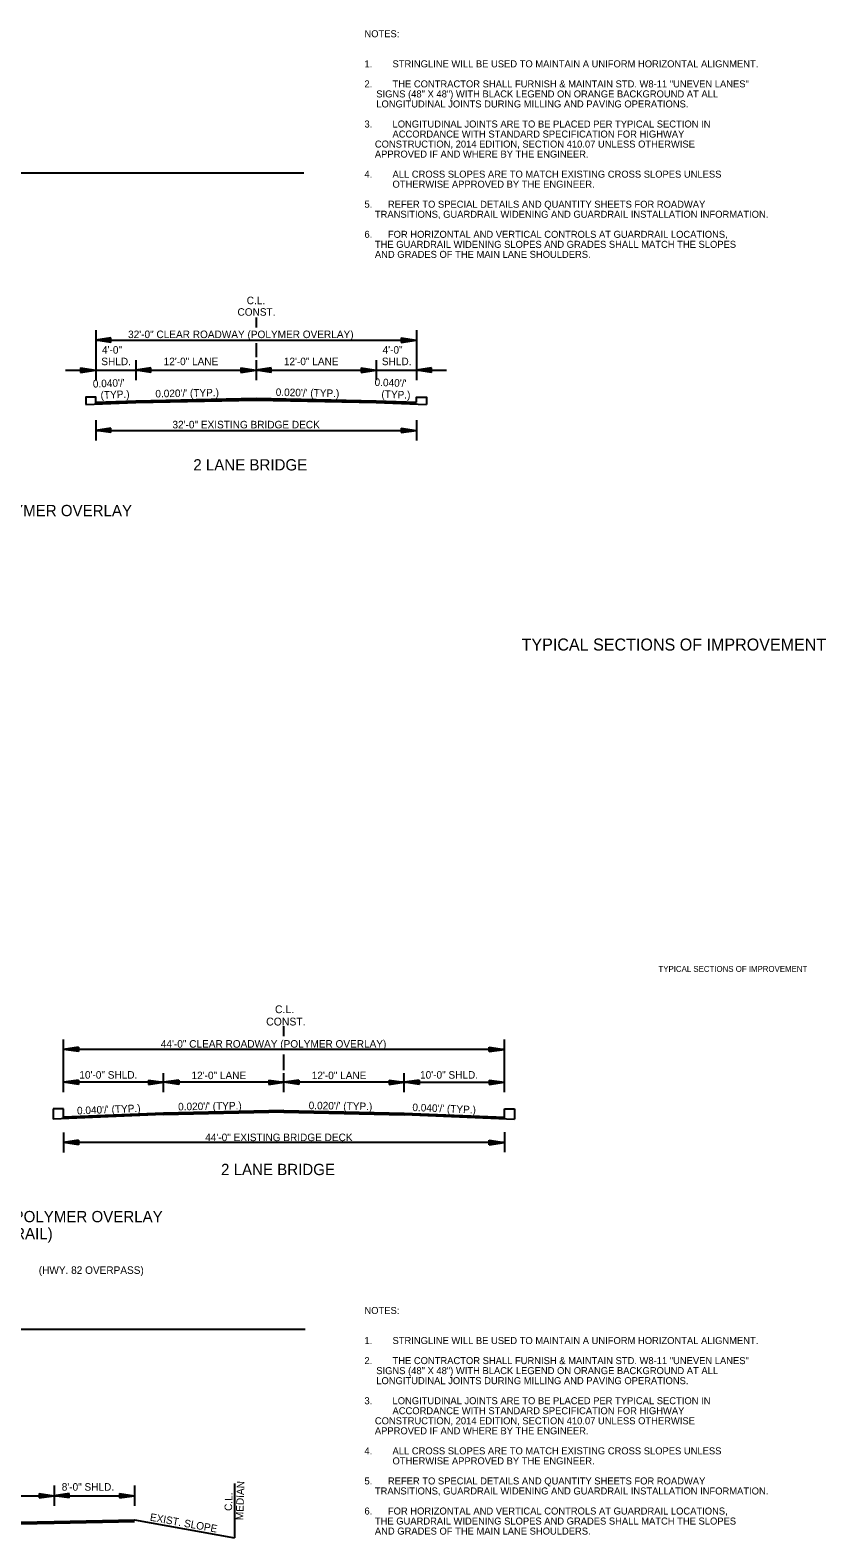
# Model space of a CAD drawing. Extents: x 545241 to 1930787, y -1971772 to 596640.
# Drawn here: x 547474 to 548268, y -1968756 to -1967253 of the extents above; entities that cross this region are included whole.
import ezdxf

# ---------------------------------------------------------------- set-up
doc = ezdxf.new("R2010")
doc.units = 0
for name, color, linetype in [('R_Border', 7, 'Continuous'), ('R_Border Notes', 7, 'Continuous'), ('R_Border Prem', 7, 'Continuous'), ('R_Draft', 7, 'Continuous')]:
    doc.layers.add(name, color=color, linetype=linetype)

# ---------------------------------------------------------------- blocks, each defined once
blk = doc.blocks.new('ARROW')
at = {"layer": 'R_Draft'}
for p, q in [((-2, 0.3), (0, 0)), ((-2, 0.3), (-2, -0.3)), ((-2, 0.25), (-0.334, 0)), ((-2, 0.199), (-0.678, 0)), ((-2, 0.149), (-1.011, 0)), ((-2, 0.097), (-1.35, 0)), ((-2, 0.047), (-1.684, 0)), ((-2, -0.3), (0, 0)), ((-2, -0.098), (-1.35, 0)), ((-2, -0.199), (-0.678, 0)), ((-2, -0.25), (-0.334, 0)), ((-2, -0.149), (-1.011, 0)), ((-2, -0.047), (-1.684, 0))]:
    blk.add_line(p, q, dxfattribs=at)

msp = doc.modelspace()

# ---------------------------------------------------------------- linework, layer by layer
at = {"layer": 'R_Border'}
for p, q in [((546718.9, -1967395.3), (547746.9, -1967395.3)), ((547699.2, -1967539.5), (547699.2, -1967549.5)), ((547539.2, -1967552), (547539.2, -1967602)), ((547859.2, -1967552), (547859.2, -1967602)), ((547539.2, -1967562), (547859.2, -1967562)), ((547699.2, -1967565), (547699.2, -1967579)), ((547579.2, -1967582), (547579.2, -1967602)), ((547699.2, -1967582), (547699.2, -1967602)), ((547819.2, -1967582), (547819.2, -1967602)), ((547509.2, -1967592), (547889.2, -1967592)), ((547539.2, -1967642), (547539.2, -1967662)), ((547859.2, -1967642), (547859.2, -1967662)), ((547539.2, -1967652), (547859.2, -1967652)), ((547507, -1968328.6), (547496.8, -1968328.6)), ((547496.8, -1968328.6), (547496.8, -1968338.8)), ((547507, -1968338), (547507, -1968328.6)), ((547947, -1968338), (547947, -1968328.6)), ((547947, -1968328.6), (547957.1, -1968328.6)), ((547957.1, -1968328.6), (547957.1, -1968338.8)), ((546720.3, -1968548.2), (547748.2, -1968548.2)), ((547497.8, -1968704.4), (547497.8, -1968724.4)), ((547577.8, -1968704.4), (547577.8, -1968724.4)), ((547677.8, -1968702.2), (547677.8, -1968756.4)), ((547177.8, -1968714.4), (547577.8, -1968714.4)), ((547577.8, -1968738.4), (547677.8, -1968756.4))]:
    msp.add_line(p, q, dxfattribs=at)
for points in [[(547539.2, -1967625.5), (547539.2, -1967619), (547529.2, -1967619), (547529.2, -1967626.2)], [(547529.2, -1967626.2), (547579.2, -1967624.2), (547699.2, -1967621.8), (547819.2, -1967624.2), (547869.2, -1967626.2)], [(547539.2, -1967624), (547579.2, -1967622.4), (547699.2, -1967620), (547819.2, -1967622.4), (547859.2, -1967624)], [(547539.2, -1967624.3), (547579.2, -1967622.7), (547699.2, -1967620.3), (547819.2, -1967622.7), (547859.2, -1967624.3)], [(547539.2, -1967624.6), (547579.2, -1967623), (547699.2, -1967620.6), (547819.2, -1967623), (547859.2, -1967624.6)], [(547539.2, -1967624.9), (547579.2, -1967623.3), (547699.2, -1967620.9), (547819.2, -1967623.3), (547859.2, -1967624.9)], [(547539.2, -1967625.2), (547579.2, -1967623.6), (547699.2, -1967621.2), (547819.2, -1967623.6), (547859.2, -1967625.2)], [(547539.2, -1967625.5), (547579.2, -1967623.9), (547699.2, -1967621.5), (547819.2, -1967623.9), (547859.2, -1967625.5)], [(547859.2, -1967624), (547859.2, -1967619), (547869.2, -1967619), (547869.2, -1967626.2)], [(547177.8, -1968748), (547257.8, -1968744.8), (547377.8, -1968742.4), (547497.8, -1968740), (547577.8, -1968738.4)], [(547177.8, -1968748.3), (547257.8, -1968745.1), (547377.8, -1968742.7), (547497.8, -1968740.3), (547577.8, -1968738.7)], [(547177.8, -1968748.6), (547257.8, -1968745.4), (547377.8, -1968743), (547497.8, -1968740.6), (547577.8, -1968739)], [(547177.8, -1968748.9), (547257.8, -1968745.7), (547377.8, -1968743.3), (547497.8, -1968740.9), (547577.8, -1968739.3)], [(547177.8, -1968749.2), (547257.8, -1968746), (547377.8, -1968743.6), (547497.8, -1968741.2), (547577.8, -1968739.6)], [(547177.8, -1968749.5), (547257.8, -1968746.3), (547377.8, -1968743.9), (547497.8, -1968741.5), (547577.8, -1968739.9)], [(547177.8, -1968749.8), (547257.8, -1968746.6), (547377.8, -1968744.2), (547497.8, -1968741.8), (547577.8, -1968740.2)]]:
    msp.add_lwpolyline(points, dxfattribs=at)
at = {"layer": 'R_Draft'}
for p, q in [((547727, -1968256.3), (547727, -1968246.3)), ((547507, -1968312.1), (547507, -1968259.4)), ((547947, -1968312.1), (547947, -1968259.4)), ((547522, -1968267.1), (547507, -1968269.3)), ((547947, -1968269.3), (547507, -1968269.3)), ((547522, -1968271.6), (547507, -1968269.3)), ((547522, -1968267.4), (547509.5, -1968269.3)), ((547522, -1968271.2), (547509.5, -1968269.3)), ((547522, -1968267.8), (547512, -1968269.3)), ((547522, -1968270.8), (547512, -1968269.3)), ((547522, -1968268.2), (547514.5, -1968269.3)), ((547522, -1968270.4), (547514.5, -1968269.3)), ((547522, -1968268.6), (547517.1, -1968269.3)), ((547522, -1968270), (547517.1, -1968269.3)), ((547522, -1968268.9), (547519.6, -1968269.3)), ((547522, -1968269.7), (547519.6, -1968269.3)), ((547522, -1968267.1), (547522, -1968271.6)), ((547897, -1968269.3), (547617, -1968269.3)), ((547727, -1968290.1), (547727, -1968274.4)), ((547932, -1968267.1), (547947, -1968269.3)), ((547932, -1968271.6), (547932, -1968267.1)), ((547932, -1968267.4), (547944.5, -1968269.3)), ((547932, -1968267.8), (547941.9, -1968269.3)), ((547932, -1968268.2), (547939.4, -1968269.3)), ((547932, -1968268.6), (547936.8, -1968269.3)), ((547932, -1968268.9), (547934.3, -1968269.3)), ((547932, -1968271.6), (547947, -1968269.3)), ((547932, -1968270), (547936.8, -1968269.3)), ((547932, -1968270.8), (547941.9, -1968269.3)), ((547932, -1968271.2), (547944.5, -1968269.3)), ((547932, -1968270.4), (547939.4, -1968269.3)), ((547932, -1968269.7), (547934.3, -1968269.3)), ((547607, -1968312.1), (547607, -1968292.9)), ((547727, -1968312.1), (547727, -1968292.9)), ((547847, -1968312.1), (547847, -1968292.9)), ((547522, -1968299.9), (547507, -1968302.1)), ((547607, -1968302.1), (547507, -1968302.1)), ((547522, -1968304.4), (547507, -1968302.1)), ((547522, -1968300.3), (547509.5, -1968302.1)), ((547522, -1968304), (547509.5, -1968302.1)), ((547522, -1968300.6), (547512, -1968302.1)), ((547522, -1968303.6), (547512, -1968302.1)), ((547522, -1968301), (547514.5, -1968302.1)), ((547522, -1968303.3), (547514.5, -1968302.1)), ((547522, -1968301.4), (547517.1, -1968302.1)), ((547522, -1968302.9), (547517.1, -1968302.1)), ((547522, -1968301.8), (547519.6, -1968302.1)), ((547522, -1968302.5), (547519.6, -1968302.1)), ((547522, -1968299.9), (547522, -1968304.4)), ((547592, -1968299.9), (547607, -1968302.1)), ((547592, -1968299.9), (547592, -1968304.4)), ((547592, -1968300.3), (547604.5, -1968302.1)), ((547592, -1968300.6), (547601.9, -1968302.1)), ((547592, -1968301), (547599.4, -1968302.1)), ((547592, -1968301.4), (547596.8, -1968302.1)), ((547592, -1968301.8), (547594.3, -1968302.1)), ((547592, -1968304.4), (547607, -1968302.1)), ((547592, -1968302.9), (547596.8, -1968302.1)), ((547592, -1968303.6), (547601.9, -1968302.1)), ((547592, -1968304), (547604.5, -1968302.1)), ((547592, -1968303.3), (547599.4, -1968302.1)), ((547592, -1968302.5), (547594.3, -1968302.1)), ((547622, -1968299.9), (547607, -1968302.1)), ((547727, -1968302.1), (547607, -1968302.1)), ((547622, -1968304.4), (547607, -1968302.1)), ((547622, -1968300.3), (547609.5, -1968302.1)), ((547622, -1968304), (547609.5, -1968302.1)), ((547622, -1968300.6), (547612, -1968302.1)), ((547622, -1968303.6), (547612, -1968302.1)), ((547622, -1968301), (547614.5, -1968302.1)), ((547622, -1968303.3), (547614.5, -1968302.1)), ((547622, -1968301.4), (547617.1, -1968302.1)), ((547622, -1968302.9), (547617.1, -1968302.1)), ((547622, -1968301.8), (547619.6, -1968302.1)), ((547622, -1968302.5), (547619.6, -1968302.1)), ((547622, -1968299.9), (547622, -1968304.4)), ((547712, -1968299.9), (547727, -1968302.1)), ((547712, -1968299.9), (547712, -1968304.4)), ((547712, -1968300.3), (547724.5, -1968302.1)), ((547712, -1968300.6), (547721.9, -1968302.1)), ((547712, -1968301), (547719.4, -1968302.1)), ((547712, -1968301.4), (547716.8, -1968302.1)), ((547712, -1968301.8), (547714.3, -1968302.1)), ((547712, -1968304.4), (547727, -1968302.1)), ((547712, -1968302.9), (547716.8, -1968302.1)), ((547712, -1968303.6), (547721.9, -1968302.1)), ((547712, -1968304), (547724.5, -1968302.1)), ((547712, -1968303.3), (547719.4, -1968302.1)), ((547712, -1968302.5), (547714.3, -1968302.1)), ((547742, -1968299.9), (547727, -1968302.1)), ((547847, -1968302.1), (547727, -1968302.1)), ((547742, -1968304.4), (547727, -1968302.1)), ((547742, -1968300.3), (547729.5, -1968302.1)), ((547742, -1968304), (547729.5, -1968302.1)), ((547742, -1968300.6), (547732, -1968302.1)), ((547742, -1968303.6), (547732, -1968302.1)), ((547742, -1968301), (547734.5, -1968302.1)), ((547742, -1968303.3), (547734.5, -1968302.1)), ((547742, -1968301.4), (547737.1, -1968302.1)), ((547742, -1968302.9), (547737.1, -1968302.1)), ((547742, -1968301.8), (547739.6, -1968302.1)), ((547742, -1968302.5), (547739.6, -1968302.1)), ((547742, -1968299.9), (547742, -1968304.4)), ((547832, -1968299.9), (547847, -1968302.1)), ((547832, -1968299.9), (547832, -1968304.4)), ((547832, -1968300.3), (547844.5, -1968302.1)), ((547832, -1968300.6), (547841.9, -1968302.1)), ((547832, -1968301), (547839.4, -1968302.1)), ((547832, -1968301.4), (547836.8, -1968302.1)), ((547832, -1968301.8), (547834.3, -1968302.1)), ((547832, -1968304.4), (547847, -1968302.1)), ((547832, -1968302.9), (547836.8, -1968302.1)), ((547832, -1968303.6), (547841.9, -1968302.1)), ((547832, -1968304), (547844.5, -1968302.1)), ((547832, -1968303.3), (547839.4, -1968302.1)), ((547832, -1968302.5), (547834.3, -1968302.1)), ((547862, -1968299.9), (547847, -1968302.1)), ((547847, -1968302.1), (547947, -1968302.1)), ((547862, -1968304.4), (547847, -1968302.1)), ((547862, -1968300.3), (547849.5, -1968302.1)), ((547862, -1968304), (547849.5, -1968302.1)), ((547862, -1968300.6), (547852, -1968302.1)), ((547862, -1968303.6), (547852, -1968302.1)), ((547862, -1968301), (547854.5, -1968302.1)), ((547862, -1968303.3), (547854.5, -1968302.1)), ((547862, -1968301.4), (547857.1, -1968302.1)), ((547862, -1968302.9), (547857.1, -1968302.1)), ((547862, -1968301.8), (547859.6, -1968302.1)), ((547862, -1968302.5), (547859.6, -1968302.1)), ((547862, -1968299.9), (547862, -1968304.4)), ((547932, -1968299.9), (547947, -1968302.1)), ((547932, -1968299.9), (547932, -1968304.4)), ((547932, -1968300.3), (547944.5, -1968302.1)), ((547932, -1968300.6), (547941.9, -1968302.1)), ((547932, -1968301), (547939.4, -1968302.1)), ((547932, -1968301.4), (547936.8, -1968302.1)), ((547932, -1968301.8), (547934.3, -1968302.1)), ((547932, -1968304.4), (547947, -1968302.1)), ((547932, -1968302.9), (547936.8, -1968302.1)), ((547932, -1968303.6), (547941.9, -1968302.1)), ((547932, -1968304), (547944.5, -1968302.1)), ((547932, -1968303.3), (547939.4, -1968302.1)), ((547932, -1968302.5), (547934.3, -1968302.1)), ((547607, -1968334.3), (547496.8, -1968338.8)), ((547607, -1968332.8), (547507, -1968336.8)), ((547607, -1968333.1), (547507, -1968337.1)), ((547607, -1968333.4), (547507, -1968337.4)), ((547607, -1968333.7), (547507, -1968337.7)), ((547607, -1968334), (547507, -1968338)), ((547727, -1968330.4), (547607, -1968332.8)), ((547727, -1968330.7), (547607, -1968333.1)), ((547727, -1968331), (547607, -1968333.4)), ((547727, -1968331.3), (547607, -1968333.7)), ((547727, -1968331.6), (547607, -1968334)), ((547727, -1968331.9), (547607, -1968334.3)), ((547727, -1968332.1), (547607, -1968334.5)), ((547727, -1968330.4), (547847, -1968332.8)), ((547727, -1968330.7), (547847, -1968333.1)), ((547727, -1968331), (547847, -1968333.4)), ((547727, -1968331.3), (547847, -1968333.7)), ((547727, -1968331.6), (547847, -1968334)), ((547727, -1968331.9), (547847, -1968334.3)), ((547727, -1968332.1), (547847, -1968334.5)), ((547847, -1968332.8), (547947, -1968336.8)), ((547847, -1968333.1), (547947, -1968337.1)), ((547847, -1968333.4), (547947, -1968337.4)), ((547847, -1968333.7), (547947, -1968337.7)), ((547847, -1968334), (547947, -1968338)), ((547847, -1968334.3), (547957.1, -1968338.8)), ((547507, -1968352.1), (547507, -1968372.1)), ((547947, -1968351.9), (547947, -1968371.9)), ((547522, -1968359.9), (547507, -1968362.1)), ((547522, -1968364.4), (547507, -1968362.1)), ((547947, -1968362.1), (547507, -1968362.1)), ((547522, -1968360.2), (547509.5, -1968362.1)), ((547522, -1968364), (547509.5, -1968362.1)), ((547522, -1968360.6), (547512, -1968362.1)), ((547522, -1968363.6), (547512, -1968362.1)), ((547522, -1968361), (547514.5, -1968362.1)), ((547522, -1968363.2), (547514.5, -1968362.1)), ((547522, -1968361.4), (547517.1, -1968362.1)), ((547522, -1968362.8), (547517.1, -1968362.1)), ((547522, -1968361.7), (547519.6, -1968362.1)), ((547522, -1968362.5), (547519.6, -1968362.1)), ((547522, -1968359.9), (547522, -1968364.4)), ((547932, -1968359.9), (547947, -1968362.1)), ((547932, -1968364.4), (547932, -1968359.9)), ((547932, -1968360.2), (547944.5, -1968362.1)), ((547932, -1968360.6), (547941.9, -1968362.1)), ((547932, -1968361), (547939.4, -1968362.1)), ((547932, -1968361.4), (547936.8, -1968362.1)), ((547932, -1968361.7), (547934.3, -1968362.1)), ((547932, -1968364.4), (547947, -1968362.1)), ((547932, -1968362.8), (547936.8, -1968362.1)), ((547932, -1968363.6), (547941.9, -1968362.1)), ((547932, -1968364), (547944.5, -1968362.1)), ((547932, -1968363.2), (547939.4, -1968362.1)), ((547932, -1968362.5), (547934.3, -1968362.1))]:
    msp.add_line(p, q, dxfattribs=at)

# ---------------------------------------------------------------- block references
at = {"layer": 'R_Border', "xscale": 7.5, "yscale": 7.5, "rotation": 180}
for p in [(547539.2, -1967562), (547579.2, -1967592), (547699.2, -1967592), (547859.2, -1967592), (547539.2, -1967652), (547497.8, -1968714.4)]:
    msp.add_blockref('ARROW', p, dxfattribs=at)
at = {"layer": 'R_Border', "xscale": 7.5, "yscale": 7.5}
for p in [(547859.2, -1967562), (547539.2, -1967592), (547699.2, -1967592), (547819.2, -1967592), (547859.2, -1967652), (547497.8, -1968714.4), (547577.8, -1968714.4)]:
    msp.add_blockref('ARROW', p, dxfattribs=at)

# ---------------------------------------------------------------- texts
at = {"layer": 'R_Border'}
for s, height, p in [('C.L.', 7.5, (547689.9, -1967526.2)), ('CONST.', 7.5, (547680.7, -1967537.7)), ('32\'-0" CLEAR ROADWAY (POLYMER OVERLAY)', 7.5, (547571.5, -1967560)), ('4\'-0"', 7.5, (547545.5, -1967575.5)), ('4\'-0"', 7.5, (547825.5, -1967575.5)), ('SHLD.', 7.5, (547544.8, -1967587)), ('12\'-0" LANE', 7.5, (547607, -1967587)), ('12\'-0" LANE', 7.5, (547727, -1967587)), ('SHLD.', 7.5, (547824.8, -1967587)), ('32\'-0" EXISTING BRIDGE DECK', 7.5, (547615.8, -1967650)), ('2 LANE BRIDGE', 11.25, (547636.6, -1967692)), ('32 FT. CLEAR ROADWAY BRIDGE - POLYMER OVERLAY', 11.25, (547171.7, -1967737.6)), ('8\'-0" SHLD.', 7.5, (547505.3, -1968709.4))]:
    msp.add_text(s, height=height, dxfattribs=at).set_placement(p)
for s, height, rotation, p in [("0.040'/'", 7.5, 2.2916, (547536.5, -1967609.4)), ("0.040'/'", 7.5, 357.7084, (547817.4, -1967607.6)), ('(TYP.)', 7.5, 2.2916, (547544.2, -1967620.6)), ("0.020'/' (TYP.)", 7.5, 1.1458, (547598.8, -1967619.2)), ("0.020'/' (TYP.)", 7.5, 358.8542, (547718.8, -1967617.6)), ('(TYP.)', 7.5, 357.7084, (547824.2, -1967619.4)), ('TYPICAL SECTIONS OF IMPROVEMENT', 12, 360, (547964.2, -1967871.6)), ('C.L.', 7.5, 88.1187, (547675.2, -1968729.7)), ('MEDIAN', 7.5, 88.1187, (547686.4, -1968738.9)), ('EXIST. SLOPE', 7.5, 349.796, (547592.9, -1968739.2))]:
    msp.add_text(s, height=height, rotation=rotation, dxfattribs=at).set_placement(p)
at = {"layer": 'R_Border Notes'}
for s, p in [('NOTES: ', (547807.4, -1967260)), ('1.', (547807.4, -1967290)), ('STRINGLINE WILL BE USED TO MAINTAIN A UNIFORM HORIZONTAL ALIGNMENT.', (547835.4, -1967290)), ('2.', (547807.4, -1967310)), ('    SIGNS (48" X 48") WITH BLACK LEGEND ON ORANGE BACKGROUND AT ALL ', (547808.8, -1967320)), ('THE CONTRACTOR SHALL FURNISH & MAINTAIN STD. W8-11 "UNEVEN LANES" ', (547835.4, -1967310)), ('    LONGITUDINAL JOINTS DURING MILLING AND PAVING OPERATIONS.', (547808.8, -1967330)), ('3.', (547807.4, -1967350)), ('LONGITUDINAL JOINTS ARE TO BE PLACED PER TYPICAL SECTION IN ', (547835.4, -1967350)), ('ACCORDANCE WITH STANDARD SPECIFICATION FOR HIGHWAY', (547835.4, -1967360)), ('    APPROVED IF AND WHERE BY THE ENGINEER.', (547807.4, -1967380)), ('    CONSTRUCTION, 2014 EDITION, SECTION 410.07 UNLESS OTHERWISE', (547807.4, -1967370)), ('4.', (547807.4, -1967400)), ('ALL CROSS SLOPES ARE TO MATCH EXISTING CROSS SLOPES UNLESS ', (547835.4, -1967400)), ('OTHERWISE APPROVED BY THE ENGINEER.', (547835.4, -1967410)), ('5.      REFER TO SPECIAL DETAILS AND QUANTITY SHEETS FOR ROADWAY', (547807.4, -1967430)), ('    TRANSITIONS, GUARDRAIL WIDENING AND GUARDRAIL INSTALLATION INFORMATION.', (547807.4, -1967440)), ('6.      FOR HORIZONTAL AND VERTICAL CONTROLS AT GUARDRAIL LOCATIONS,', (547807.4, -1967460)), ('    THE GUARDRAIL WIDENING SLOPES AND GRADES SHALL MATCH THE SLOPES', (547807.4, -1967470)), ('    AND GRADES OF THE MAIN LANE SHOULDERS.  ', (547807.4, -1967480)), ('NOTES: ', (547807.4, -1968533.2)), ('1.', (547807.4, -1968563.2)), ('STRINGLINE WILL BE USED TO MAINTAIN A UNIFORM HORIZONTAL ALIGNMENT.', (547835.4, -1968563.2)), ('2.', (547807.4, -1968583.2)), ('THE CONTRACTOR SHALL FURNISH & MAINTAIN STD. W8-11 "UNEVEN LANES" ', (547835.4, -1968583.2)), ('    SIGNS (48" X 48") WITH BLACK LEGEND ON ORANGE BACKGROUND AT ALL ', (547808.8, -1968593.2)), ('    LONGITUDINAL JOINTS DURING MILLING AND PAVING OPERATIONS.', (547808.8, -1968603.2)), ('3.', (547807.4, -1968623.2)), ('LONGITUDINAL JOINTS ARE TO BE PLACED PER TYPICAL SECTION IN ', (547835.4, -1968623.2)), ('    CONSTRUCTION, 2014 EDITION, SECTION 410.07 UNLESS OTHERWISE', (547807.4, -1968643.2)), ('ACCORDANCE WITH STANDARD SPECIFICATION FOR HIGHWAY', (547835.4, -1968633.2)), ('    APPROVED IF AND WHERE BY THE ENGINEER.', (547807.4, -1968653.2)), ('4.', (547807.4, -1968673.2)), ('ALL CROSS SLOPES ARE TO MATCH EXISTING CROSS SLOPES UNLESS ', (547835.4, -1968673.2)), ('OTHERWISE APPROVED BY THE ENGINEER.', (547835.4, -1968683.2)), ('5.      REFER TO SPECIAL DETAILS AND QUANTITY SHEETS FOR ROADWAY', (547807.4, -1968703.2)), ('    TRANSITIONS, GUARDRAIL WIDENING AND GUARDRAIL INSTALLATION INFORMATION.', (547807.4, -1968713.2)), ('6.      FOR HORIZONTAL AND VERTICAL CONTROLS AT GUARDRAIL LOCATIONS,', (547807.4, -1968733.2)), ('    THE GUARDRAIL WIDENING SLOPES AND GRADES SHALL MATCH THE SLOPES', (547807.4, -1968743.2)), ('    AND GRADES OF THE MAIN LANE SHOULDERS.  ', (547807.4, -1968753.2))]:
    msp.add_text(s, height=7, dxfattribs=at).set_placement(p)
at = {"layer": 'R_Border Prem'}
msp.add_text('TYPICAL SECTIONS OF IMPROVEMENT', height=5.862, rotation=360, dxfattribs=at).set_placement((548100.8, -1968192))
at = {"layer": 'R_Draft'}
for s, height, p in [('C.L.', 7.8, (547718.1, -1968233.2)), ('CONST.', 7.8, (547709.3, -1968245.5)), ('44\'-0" CLEAR ROADWAY (POLYMER OVERLAY)', 7.5, (547604.2, -1968267.6)), ('10\'-0" SHLD.', 7.5, (547522.9, -1968298.5)), ('12\'-0" LANE', 7.5, (547634.8, -1968299)), ('12\'-0" LANE', 7.5, (547754.8, -1968299)), ('10\'-0" SHLD.', 7.5, (547862.9, -1968298.5)), ('44\'-0" EXISTING BRIDGE DECK', 7.5, (547648.5, -1968360.8)), ('2 LANE BRIDGE', 11.25, (547664.3, -1968394.7)), ('44 FT. CLEAR ROADWAY BRIDGE - POLYMER OVERLAY', 11.25, (547202.3, -1968441.7)), ('(NEW GUARDRAIL)', 11.25, (547359.2, -1968458.6)), ('(HWY. 82 OVERPASS)', 7.5, (547482.4, -1968493.2))]:
    msp.add_text(s, height=height, dxfattribs=at).set_placement(p)
for s, rotation, p in [("0.020'/' (TYP.)", 0.9719, (547621.5, -1968330.2)), ("0.020'/' (TYP.)", 359.0281, (547751.7, -1968328.9)), ("0.040'/' (TYP.)", 2.2906, (547520.7, -1968334.2)), ("0.040'/' (TYP.)", 357.7094, (547855.1, -1968330.8))]:
    msp.add_text(s, height=7.5, rotation=rotation, dxfattribs=at).set_placement(p)

doc.saveas('drawing.dxf')
